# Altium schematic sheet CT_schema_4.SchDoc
size 368 x 309 mm
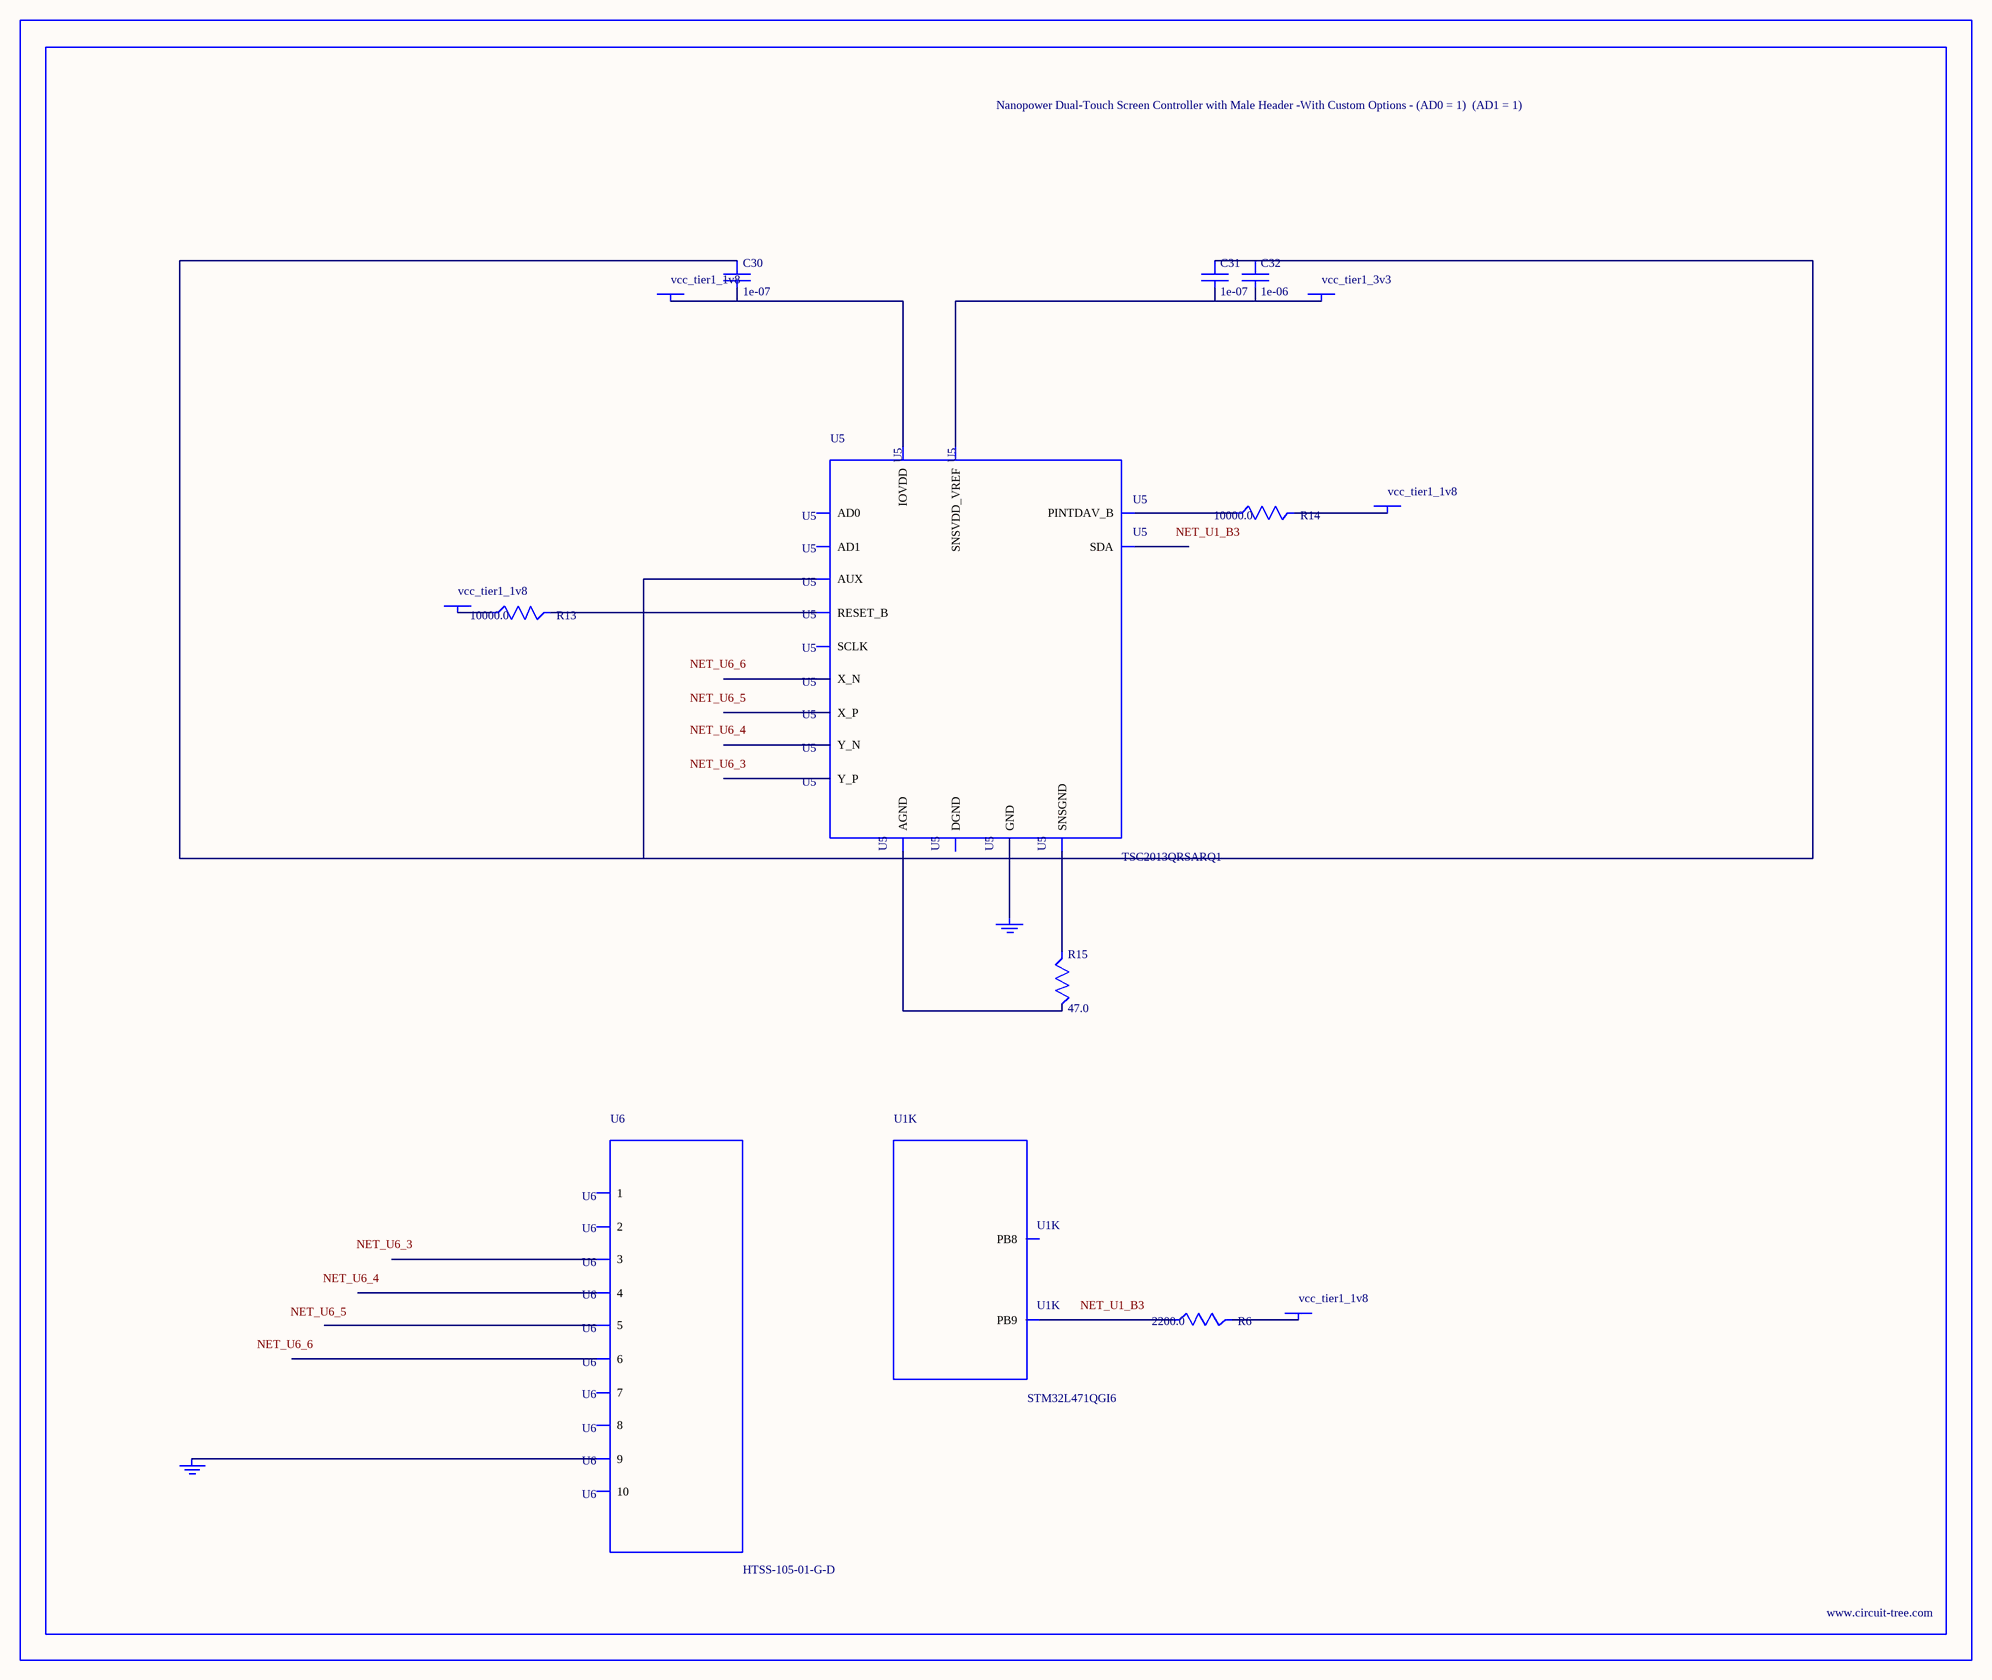
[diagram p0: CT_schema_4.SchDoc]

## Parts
BORDER3  (no value)
C30  1e-07  [C0402]
C31  1e-07  [C0402]
C32  1e-06  [C0603]
GND_INSTANCE_3_0  (no value)
GND_INSTANCE_3_1  (no value)
POWER_INSTANCE_3_0  vcc_tier1_1v8
POWER_INSTANCE_3_1  vcc_tier1_1v8
POWER_INSTANCE_3_2  vcc_tier1_1v8
POWER_INSTANCE_3_3  vcc_tier1_3v3
POWER_INSTANCE_3_4  vcc_tier1_1v8
R6  2200.0  [R0603]
R13  10000.0  [R0603]
R14  10000.0  [R0603]
R15  47.0  [R0603]
U1  STM32L471QGI6  [UFBGA132]  (part K of 12)
U5  TSC2013QRSARQ1  [QFN65P400X400X100-17N]
U6  HTSS-105-01-G-D  [HTSS-105-01-G-D]

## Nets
NetC30_1: C30.1 C31.1 C32.1 R15.1 R15.2 U5.8(AUX) U5.9(AGND) U5.15(SNSGND)
NetC30_2: C30.2 POWER_INSTANCE_3_2.0(PWR) U5.7(IOVDD)
NetC31_2: C31.2 C32.2 POWER_INSTANCE_3_3.0(PWR) U5.10(SNSVDD_VREF)
NetGND_INSTANCE_3_0_0: GND_INSTANCE_3_0.0(GND) U5.17(GND)
NetGND_INSTANCE_3_1_0: GND_INSTANCE_3_1.0(GND) U6.9
NetPOWER_INSTANCE_3_0_0: POWER_INSTANCE_3_0.0(PWR) R14.2
NetPOWER_INSTANCE_3_1_0: POWER_INSTANCE_3_1.0(PWR) R13.1
NetPOWER_INSTANCE_3_4_0: POWER_INSTANCE_3_4.0(PWR) R6.2
NetR6_1: R6.1 U1.B3(PB9)
NetR13_2: R13.2 U5.5(RESET_B)
NetR14_1: R14.1 U5.4(PINTDAV_B)

Not connected (* = marked no-connect by the designer): U1 A3(PB8); U5 1(SDA) 2(SCLK) 3(AD1) 6(DGND) 11(X_P) 12(Y_P) 13(X_N) 14(Y_N) 16(AD0); U6 1 2 3 4 5 6 7 8 10

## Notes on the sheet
- Labels drawn without touching a wire or pin: NET_U1_B3, NET_U6_3, NET_U6_4, NET_U6_5, NET_U6_6

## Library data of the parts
BORDER3 = BORDER_PAGE3
C30 C31 = C0402C104K3RACTU
C32 = C0603C105K3RACTU
GND_INSTANCE_3_0 GND_INSTANCE_3_1 = GND
POWER_INSTANCE_3_0-POWER_INSTANCE_3_4 = PWR
R6 = RC0603JR-072K2L
R13 R14 = RC0603JR-0710KL
R15 = RC0603JR-0747RL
